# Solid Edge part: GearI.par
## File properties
Author: Chalangana Oshan
Template: iso metric part.par
Last saved by: Nimesh.N
Revision: 24
Application: Solid Edge
Density: 7250.000 kg/m^3
Accuracy: 0.990
Username: Nimesh.N
Material: Iron:0.6025 , EN-GJL-250
Face Style: Gray
Fill Style: ANSI31(Iron)
Grouping: Iron\Gray Cast Iron
LibraryName: Materials-DIN
Coef. of Thermal Exp: 1.05e-05
Thermal Conductivity: 58.0
Specific Heat: 460.0
Modulus of Elasticity: 120000003072.0
Poisson's Ratio: 0.26
Yield Stress: 165593984.0
Ultimate Stress: 250000000.0
Elongation: 0.0
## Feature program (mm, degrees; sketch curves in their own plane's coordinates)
sketch for "unnamed Protrusion 1" plane through (0, 0, 0) normal (0, 0, 1) x-axis (1, 0, 0)
  circle centre (0, 0) radius 100
extrude "unnamed Protrusion 1" add finite 130 along -normal
sketch used by "unnamed Cutout 1" plane through (0, 0, 0) normal (0, 0, 1) x-axis (1, 0, 0)
  line (0, 0) -> (-17.3648, 98.4808)
  line (0, 0) -> (-14.4932, 98.9442)
  line (-3.3805, 77.4262) -> (3.3805, 77.4262)
  arc centre (-61.1504, 61.2201) radius 60 from (-14.4932, 98.9442) to (-3.3805, 77.4262) cw
  arc centre (61.1504, 61.2201) radius 60 from (14.4932, 98.9442) to (3.3805, 77.4262) ccw
extrude "unnamed Cutout 1" cut through along -normal
pattern "unnamed Pattern 1" of "unnamed Cutout 1"
pattern "unnamed Pattern 2"
sketch for "unnamed Cutout 2" plane through (0, 0, 0) normal (0, 0, 1) x-axis (0.173648, 0.984808, 0)
extrude "unnamed Cutout 2" cut through along -normal
sketch for "unnamed Cutout 3" plane through (0, 0, 0) normal (0, 0, 1) x-axis (0.173648, 0.984808, 0)
extrude "unnamed Cutout 3" cut through along -normal
sketch for "ExtrudedCutout_7" plane through (-38.0136, 6.7028, -9) normal (0.984808, -0.173648, 0) x-axis (0.173648, 0.984808, 0)
extrude "ExtrudedCutout_7" cut finite 14.6335 along +normal
Other named dimensions: "ExtrudedSurface_3": FiniteDepth = 130 mm
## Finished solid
Body 1: sheet body, 1 face, 2 edges, 0 vertices.
  Faces by surface: cylinder 1
  Edges by curve: circle 2
Body 2: solid body, 78 faces, 228 edges, 152 vertices.
  Faces by surface: cylinder 55, plane 23
  Edges by curve: line 118, circle 110
Bounding box of the edges (mm): 200.000 x 197.888 x 130.000, from (-100, -98.9442, -130) to (100, 98.9442, 0).
Cylindrical faces by radius (mm): R34 x1, R60 x36, R90 x1, R100 x18
Planar faces by outward normal: +y 1, +z 1, -y 1, -z 1, oblique 19
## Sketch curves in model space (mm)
line (0, 0, 0) -> (4.3619, 99.9048, 0)
line (0, 0, 0) -> (-4.3619, 99.9048, 0)
arc centre (61.1504, 61.2201, 0) radius 60 from (14.4932, 98.9442, 0) through (7.8399, 88.7517, 0) to (3.3805, 77.4262, 0)
line (-3.3805, 77.4262, 0) -> (3.3805, 77.4262, 0)
arc centre (-61.1504, 61.2201, 0) radius 60 from (-14.4932, 98.9442, 0) through (-7.8399, 88.7517, 0) to (-3.3805, 77.4262, 0)
line (0, 0, 0) -> (-14.4932, 98.9442, 0)
line (0, 0, 0) -> (-17.3648, 98.4808, 0)
line (0, 0, 0) -> (-17.3648, 98.4808, 0)
circle centre (0, 0, 0) radius 100
circle centre (0, 0, 0) radius 90
circle centre (0, 0, 0) radius 77.5
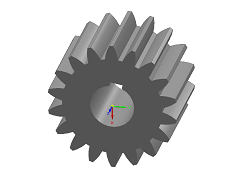
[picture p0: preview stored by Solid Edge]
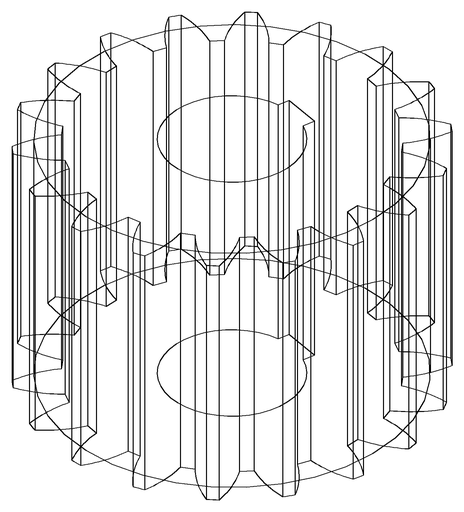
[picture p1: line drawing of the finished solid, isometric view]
